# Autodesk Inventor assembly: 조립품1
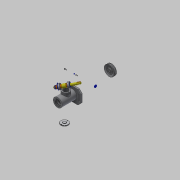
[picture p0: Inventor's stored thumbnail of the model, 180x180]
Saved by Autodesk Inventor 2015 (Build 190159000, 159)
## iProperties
Created: 2017-10
Part Number: 조립품1
Document SubType Name: Assembly
Designer: SCD-A15
Author: SCD-A15
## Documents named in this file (20)
- C:\Users\SCD-A15\Desktop\471007V1028\조립품1.iam
- C:\Users\SCD-A15\Desktop\471007V1028\본체.ipt
- C:\Users\SCD-A15\Desktop\471007V1028\너트 M10.ipt
- C:\Users\SCD-A15\Desktop\471007V1028\멈춤링 15 x 1.ipt
- C:\Users\SCD-A15\Desktop\471007V1028\멈춤링 35x1.6.ipt
- C:\Users\SCD-A15\Desktop\471007V1028\베어링 15 x 35 x 11.ipt
- C:\Users\SCD-A15\Desktop\471007V1028\볼트 M4 x 10.ipt
- C:\Users\SCD-A15\Desktop\471007V1028\부시1.ipt
- C:\Users\SCD-A15\Desktop\471007V1028\부시2.ipt
- C:\Users\SCD-A15\Desktop\471007V1028\사이드 커버.ipt
- 사이드 커버.ipt
- C:\Users\SCD-A15\Desktop\471007V1028\십자볼트 M3 x 10.ipt
- C:\Users\SCD-A15\Desktop\471007V1028\오일 실 15 25 7.ipt
- C:\Users\SCD-A15\Desktop\471007V1028\와셔 3x6.ipt
- C:\Users\SCD-A15\Desktop\471007V1028\와셔 4x16.ipt
- C:\Users\SCD-A15\Desktop\471007V1028\와셔 10x21.ipt
- C:\Users\SCD-A15\Desktop\471007V1028\축.ipt
- C:\Users\SCD-A15\Desktop\471007V1028\키 4 x 4 x 18.ipt
- C:\Users\SCD-A15\Desktop\471007V1028\탑 커버.ipt
- C:\Users\SCD-A15\Desktop\471007V1028\V-벨트풀리.ipt
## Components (2 placed, 2 different names)
1. ISO 4017 M4 x 10:1
2. V-벨트풀리:1
